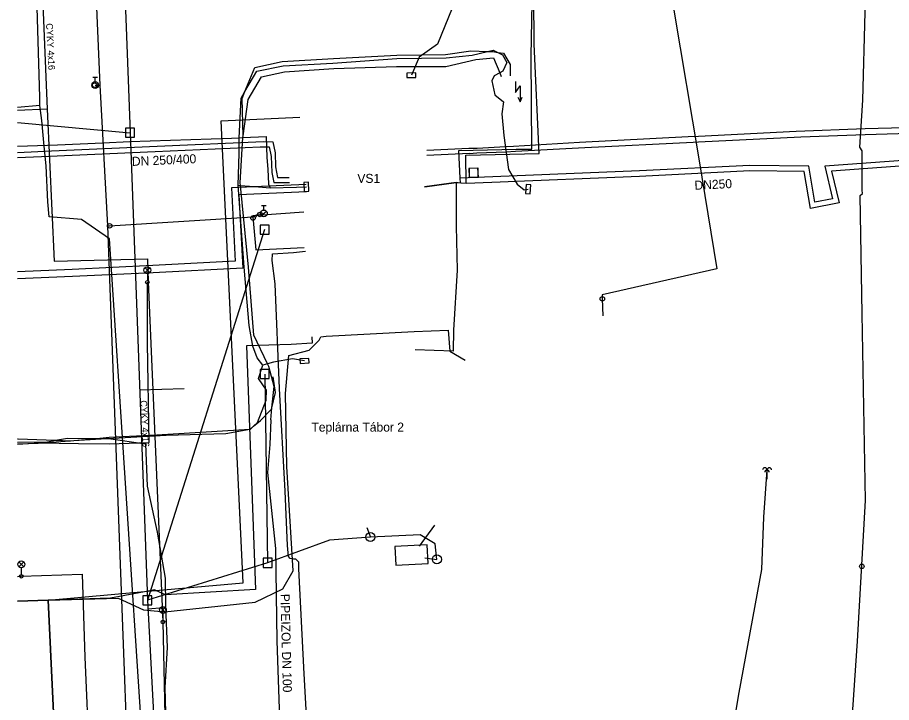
# Model space of a CAD drawing. Extents: x -736399 to -735926, y -1118992 to -1118244.
# Drawn here: x -736391.1 to -736294.2, y -1118749.6 to -1118673.7 of the extents above; entities that cross this region are included whole.
import ezdxf

# ---------------------------------------------------------------- set-up
doc = ezdxf.new("R2010")
doc.units = 0
for name, color, linetype in [('Hydranty', 7, 'Continuous'), ('Kabelovody skutečný průběh', 7, 'Continuous'), ('Kabelová skříň', 7, 'Continuous'), ('Kabelové skříně NN', 7, 'Continuous'), ('Kabelové vedení NN', 7, 'Continuous'), ('Kabelové vedení VN', 7, 'Continuous'), ('Kabelové vedení VO', 7, 'Continuous'), ('Kanalizační přípojky', 7, 'Continuous'), ('Kanalizační stoka', 7, 'Continuous'), ('Kanalizační šachty', 7, 'Continuous'), ('Nadz_ teplovodní potrubí', 7, 'Continuous'), ('Neurčené_doplňkové prvky', 7, 'Continuous'), ('Objekty nadzemní', 7, 'Continuous'), ('Osa trasy kynety', 7, 'Continuous'), ('Označník', 7, 'Continuous'), ('Plynová šoupata', 7, 'Continuous'), ('Podz_ teplovodní potrubí', 7, 'Continuous'), ('Popis teplovodu', 7, 'Continuous'), ('Popis VO', 7, 'Continuous'), ('Povrchové znaky VO', 7, 'Continuous'), ('STL plynovod', 7, 'Continuous'), ('Teplovodní kanál', 7, 'Continuous'), ('Teplovodní šachty', 7, 'Continuous'), ('Trafostanice_ rozvodny', 7, 'Continuous'), ('Vod přípojky-voda pitná', 7, 'Continuous'), ('Vod přípojky-voda užitková', 7, 'Continuous'), ('Vodovodní řad', 7, 'Continuous'), ('Vodovodní šoupata', 7, 'Continuous')]:
    doc.layers.add(name, color=color, linetype=linetype)

msp = doc.modelspace()

# ---------------------------------------------------------------- linework, layer by layer
at = {"layer": 'Hydranty'}
for p, q in [((-736382.69, -1118680.285), (-736382.19, -1118680.285)), ((-736382.44, -1118680.785), (-736382.44, -1118680.285)), ((-736364.034, -1118695.611), (-736363.444, -1118695.148)), ((-736363.99, -1118694.505), (-736363.49, -1118694.505)), ((-736363.74, -1118695.005), (-736363.74, -1118694.505))]:
    msp.add_line(p, q, dxfattribs=at)
for centre in [(-736382.44, -1118681.16), (-736363.74, -1118695.38)]:
    msp.add_circle(centre, 0.375, dxfattribs=at)
at = {"layer": 'Kabelovody skutečný průběh'}
for points in [[(-736387.66, -1118738.22), (-736391.053, -1118738.342)], [(-736383.35, -1118828.51), (-736387.66, -1118738.22)]]:
    msp.add_lwpolyline(points, dxfattribs=at)
at = {"layer": 'Kabelová skříň'}
msp.add_lwpolyline([(-736347.884, -1118680.332), (-736346.884, -1118680.308), (-736346.896, -1118679.808), (-736347.896, -1118679.832)], close=True, dxfattribs=at)
at = {"layer": 'Kabelové skříně NN'}
for points in [[(-736359.297, -1118691.95), (-736359.262, -1118692.949), (-736358.762, -1118692.931), (-736358.797, -1118691.932)], [(-736334.664, -1118692.193), (-736334.734, -1118693.191), (-736334.235, -1118693.226), (-736334.165, -1118692.228)], [(-736358.764, -1118711.444), (-736359.762, -1118711.496), (-736359.736, -1118711.996), (-736358.738, -1118711.943)]]:
    msp.add_lwpolyline(points, close=True, dxfattribs=at)
at = {"layer": 'Kabelové vedení NN'}
for points in [[(-736366.49, -1118687), (-736366.27, -1118682.61), (-736365.836, -1118681.872), (-736364.51, -1118679.62), (-736361.62, -1118679.03), (-736356.1, -1118678.73), (-736348.99, -1118678.23), (-736343.52, -1118678.15), (-736340.67, -1118677.83), (-736338.971, -1118677.432), (-736338.32, -1118677.28), (-736337.802, -1118677.539), (-736337.28, -1118677.8), (-736336.82, -1118678.64), (-736337.25, -1118679.62), (-736337.597, -1118679.804), (-736338.23, -1118680.14), (-736338.46, -1118680.68), (-736338.16, -1118682.23), (-736337.17, -1118683.03)], [(-736337.17, -1118683.03), (-736337.38, -1118684.36), (-736337.13, -1118686.76), (-736336.62, -1118690.51), (-736335.66, -1118692.13), (-736334.91, -1118692.75), (-736334.45, -1118692.71)], [(-736391.053, -1118687.946), (-736386.62, -1118687.78), (-736381.61, -1118687.56), (-736378.61, -1118687.43), (-736367.34, -1118687.04), (-736366.49, -1118687)], [(-736366.58, -1118692.25), (-736366.48, -1118688.73), (-736366.49, -1118687)], [(-736366.49, -1118687), (-736366.061, -1118686.981), (-736363.49, -1118686.87), (-736363.43, -1118689.2), (-736363.32, -1118690.48), (-736363.23, -1118692.13), (-736363.04, -1118692.53)], [(-736363.84, -1118712.19), (-736364.5, -1118711.37), (-736364.96, -1118710.1), (-736365.37, -1118707.79), (-736365.92, -1118701.35), (-736366.58, -1118692.25)], [(-736366.58, -1118692.25), (-736366.332, -1118692.27), (-736364.34, -1118692.43), (-736363.04, -1118692.53)], [(-736363.04, -1118692.53), (-736360.12, -1118692.46), (-736359.03, -1118692.44)], [(-736359.25, -1118711.72), (-736360.57, -1118711.48), (-736362.69, -1118711.88), (-736363.34, -1118712.055), (-736363.84, -1118712.19)], [(-736391.053, -1118720.896), (-736388.76, -1118720.85), (-736385.259, -1118720.587), (-736384.794, -1118720.552), (-736384.23, -1118720.51), (-736381.184, -1118720.327), (-736381.07, -1118720.32), (-736374.58, -1118719.94), (-736367.96, -1118719.76), (-736365.315, -1118719.275), (-736365.226, -1118719.258), (-736365.18, -1118719.25), (-736364.883, -1118718.973), (-736364.44, -1118718.56), (-736363.5, -1118716.08), (-736363.46, -1118714.98), (-736364.32, -1118713.68), (-736363.84, -1118712.19)], [(-736391.053, -1118720.718), (-736387.71, -1118720.69), (-736386.839, -1118720.524), (-736385.5, -1118720.27), (-736382.273, -1118720.313), (-736381.184, -1118720.327), (-736380.95, -1118720.33), (-736376.88, -1118720.92), (-736376.68, -1118725.6), (-736375.58, -1118730.69), (-736374.68, -1118735.79), (-736374.63, -1118738.91), (-736374.46, -1118743.49), (-736374.71, -1118747.93), (-736374.63, -1118750.7)]]:
    msp.add_lwpolyline(points, dxfattribs=at)
at = {"layer": 'Kabelové vedení VN'}
for points in [[(-736366.05, -1118686.8), (-736366.15, -1118682.63), (-736365.836, -1118681.872), (-736364.74, -1118679.23), (-736361.73, -1118678.54), (-736356.03, -1118678.2), (-736349.01, -1118677.86), (-736343.61, -1118677.78), (-736340.81, -1118677.38), (-736338.971, -1118677.432), (-736338.35, -1118677.45), (-736337.802, -1118677.539), (-736337.18, -1118677.64), (-736336.46, -1118678.88), (-736336.43, -1118680.15)], [(-736366.05, -1118686.8), (-736365.5, -1118682.74), (-736364.02, -1118680.24), (-736361.47, -1118679.71), (-736356, -1118679.33), (-736349.06, -1118679.09), (-736343.56, -1118679.09), (-736340.26, -1118678.34), (-736338.28, -1118678.15), (-736337.597, -1118679.804), (-736337.43, -1118680.21)], [(-736362.98, -1118718.26), (-736362.851, -1118716.939), (-736362.62, -1118714.56), (-736363.2, -1118712.35), (-736363.34, -1118712.055), (-736364.86, -1118708.86), (-736365.45, -1118701.34), (-736366.332, -1118692.27), (-736366.36, -1118691.98), (-736366.061, -1118686.981), (-736366.05, -1118686.8)], [(-736391.053, -1118720.36), (-736390.97, -1118720.36), (-736386.839, -1118720.524), (-736385.259, -1118720.587), (-736385.19, -1118720.59), (-736384.794, -1118720.552), (-736382.273, -1118720.313), (-736380.88, -1118720.18), (-736375.6, -1118719.93), (-736365.315, -1118719.275), (-736365.24, -1118719.27), (-736365.226, -1118719.258), (-736364.883, -1118718.973), (-736364.11, -1118718.33), (-736362.88, -1118717.06), (-736362.851, -1118716.939), (-736362.45, -1118715.24), (-736362.7, -1118713.48)], [(-736362.98, -1118718.26), (-736363.1, -1118720.97), (-736363.33, -1118724.1), (-736362.46, -1118732.51), (-736362.31, -1118742.76), (-736361.97, -1118752.45), (-736361.76, -1118760.37), (-736361.36, -1118768.45), (-736360.75, -1118781.08), (-736359.99, -1118796.77)]]:
    msp.add_lwpolyline(points, dxfattribs=at)
at = {"layer": 'Kabelové vedení VO'}
for points in [[(-736256.37, -1118617.77), (-736263.92, -1118623.01), (-736272.5, -1118630.07), (-736283.17, -1118636.62), (-736294.38, -1118641.55), (-736307.63, -1118648.53), (-736322.64, -1118657.67), (-736334.66, -1118664.32), (-736340.57, -1118666.94), (-736342.07, -1118670.59), (-736344.5, -1118676.64), (-736346.53, -1118678.08), (-736347.39, -1118680.07)], [(-736388.296, -1118671.266), (-736387.755, -1118683.837)], [(-736387.755, -1118683.837), (-736391.053, -1118683.979)], [(-736387.755, -1118683.837), (-736386.988, -1118700.659), (-736376.66, -1118700.413), (-736376.57, -1118702.96)], [(-736391.053, -1118720.945), (-736388.6, -1118720.81), (-736384.28, -1118720.87), (-736380.9, -1118720.91), (-736376.47, -1118720.76), (-736376.63, -1118709.75), (-736376.66, -1118703.01)], [(-736376.57, -1118702.96), (-736374.93, -1118740.65)], [(-736391.053, -1118735.606), (-736390.63, -1118735.59), (-736383.9, -1118735.35), (-736383.59, -1118744.54), (-736383.1, -1118755.62), (-736382.7, -1118765.21), (-736382.5, -1118768.83), (-736391.053, -1118769.14)], [(-736374.93, -1118740.65), (-736374.37, -1118766.6)]]:
    msp.add_lwpolyline(points, dxfattribs=at)
at = {"layer": 'Kanalizační přípojky'}
for points in [[(-736372.58, -1118714.82), (-736377.52, -1118714.95)], [(-736346.49, -1118732.24), (-736344.78, -1118729.94)], [(-736344.57, -1118733.72), (-736344.74, -1118732), (-736346.42, -1118731.01), (-736351.93, -1118731.24)], [(-736351.93, -1118731.24), (-736356.48, -1118731.59), (-736363.33, -1118734.1)], [(-736345.92, -1118733.53), (-736344.57, -1118733.72)], [(-736374.86, -1118739.1), (-736376.6, -1118739.24)]]:
    msp.add_lwpolyline(points, dxfattribs=at)
at = {"layer": 'Kanalizační stoka'}
for points in [[(-736379.98, -1118649.4), (-736378.58, -1118686.44)], [(-736391.053, -1118685.317), (-736378.58, -1118686.44)], [(-736378.58, -1118686.44), (-736376.65, -1118738.25)], [(-736363.66, -1118697.17), (-736376.65, -1118738.25)], [(-736363.65, -1118713.19), (-736363.33, -1118734.1)], [(-736363.33, -1118734.1), (-736376.65, -1118738.25)], [(-736376.65, -1118738.25), (-736374.7, -1118775.25), (-736374.15, -1118785.83), (-736373.94, -1118789.8)]]:
    msp.add_lwpolyline(points, dxfattribs=at)
at = {"layer": 'Kanalizační šachty'}
for p, q in [((-736378.08, -1118685.94), (-736379.08, -1118685.94)), ((-736379.08, -1118685.94), (-736379.08, -1118686.94)), ((-736378.08, -1118686.94), (-736378.08, -1118685.94)), ((-736379.08, -1118686.94), (-736378.08, -1118686.94)), ((-736363.16, -1118696.67), (-736364.16, -1118696.67)), ((-736364.16, -1118696.67), (-736364.16, -1118697.67)), ((-736363.16, -1118697.67), (-736363.16, -1118696.67)), ((-736364.16, -1118697.67), (-736363.16, -1118697.67)), ((-736363.15, -1118712.69), (-736364.15, -1118712.69)), ((-736364.15, -1118712.69), (-736364.15, -1118713.69)), ((-736363.15, -1118713.69), (-736363.15, -1118712.69)), ((-736364.15, -1118713.69), (-736363.15, -1118713.69)), ((-736362.83, -1118733.6), (-736363.83, -1118733.6)), ((-736363.83, -1118733.6), (-736363.83, -1118734.6)), ((-736362.83, -1118734.6), (-736362.83, -1118733.6)), ((-736363.83, -1118734.6), (-736362.83, -1118734.6)), ((-736376.15, -1118737.75), (-736377.15, -1118737.75)), ((-736377.15, -1118737.75), (-736377.15, -1118738.75)), ((-736376.15, -1118738.75), (-736376.15, -1118737.75)), ((-736377.15, -1118738.75), (-736376.15, -1118738.75))]:
    msp.add_line(p, q, dxfattribs=at)
for centre in [(-736351.93, -1118731.24), (-736344.57, -1118733.72)]:
    msp.add_circle(centre, 0.5, dxfattribs=at)
at = {"layer": 'Nadz_ teplovodní potrubí'}
for p, q in [((-736341.02, -1118688.2), (-736345.69, -1118688.4)), ((-736340.95, -1118688.75), (-736345.68, -1118688.96))]:
    msp.add_line(p, q, dxfattribs=at)
at = {"layer": 'Neurčené_doplňkové prvky'}
msp.add_line((-736307.97, -1118724.81), (-736307.97, -1118723.81), dxfattribs=at)
msp.add_lwpolyline([(-736318.09, -1118771.38), (-736313.65, -1118770.73), (-736313.25, -1118770.19), (-736313.01, -1118760.09), (-736311.06, -1118748.47), (-736308.55, -1118734.85), (-736308.32, -1118729.04), (-736307.97, -1118723.81)], dxfattribs=at)
for centre in [(-736308.22, -1118723.81), (-736307.97, -1118724.06), (-736307.72, -1118723.81)]:
    msp.add_arc(centre, 0.25, 0, 179.99999, dxfattribs=at)
at = {"layer": 'Objekty nadzemní'}
msp.add_lwpolyline([(-736349.11, -1118734.35), (-736345.53, -1118734.16), (-736345.66, -1118732.11), (-736349.23, -1118732.28), (-736349.11, -1118734.35)], dxfattribs=at)
at = {"layer": 'Osa trasy kynety'}
for points in [[(-736375.31, -1118826.617), (-736374.08, -1118826.617), (-736374.31, -1118812.667), (-736376.24, -1118777.737), (-736377.23, -1118753.457), (-736380.84, -1118698.187), (-736383.94, -1118696.047), (-736387.54, -1118695.767), (-736387.68, -1118694.087), (-736387.86, -1118690.097), (-736388.09, -1118687.917), (-736388.36, -1118685.097), (-736388.566, -1118683.41), (-736388.56, -1118682.517), (-736389.25, -1118660.127), (-736390.33, -1118624.317), (-736390.55, -1118620.227), (-736390.6, -1118618.137), (-736390.87, -1118614.807), (-736390.942, -1118613.428), (-736391.053, -1118611.927)], [(-736388.566, -1118683.41), (-736391.053, -1118683.631)], [(-736387.66, -1118738.22), (-736376.58, -1118737.24), (-736375.73, -1118737.16), (-736366.05, -1118736.3), (-736368.46, -1118685.11), (-736359.77, -1118684.71)], [(-736357.43, -1118709.04), (-736356.82, -1118709), (-736347.1, -1118708.45), (-736343.33, -1118708.32)], [(-736343.33, -1118708.32), (-736343.12, -1118710.63), (-736341.44, -1118711.63)], [(-736358.43, -1118709.06), (-736358.4, -1118709.75), (-736360.72, -1118709.9), (-736365.68, -1118710.04), (-736364.68, -1118737.07), (-736374.64, -1118737.65), (-736375.73, -1118737.16), (-736375.87, -1118737.1), (-736376.58, -1118737.24), (-736380.73, -1118738.03), (-736387.66, -1118738.22)], [(-736387.66, -1118738.22), (-736379.91, -1118738.03), (-736377.07, -1118739.3), (-736374.71, -1118739.52), (-736364.7, -1118738.45), (-736361.65, -1118736.97), (-736360.48, -1118734.97), (-736361.19, -1118723.43), (-736361.33, -1118715.33), (-736360.99, -1118711.14), (-736358.73, -1118710.53), (-736357.62, -1118709.42)], [(-736357.62, -1118709.42), (-736357.43, -1118709.04)], [(-736391.053, -1118738.342), (-736387.66, -1118738.22)], [(-736387.66, -1118738.22), (-736383.35, -1118828.51)]]:
    msp.add_lwpolyline(points, dxfattribs=at)
at = {"layer": 'Označník'}
for radius in [0.25, 0.0005]:
    msp.add_circle((-736297.461, -1118734.493), radius, dxfattribs=at)
at = {"layer": 'Plynová šoupata'}
msp.add_circle((-736326.233, -1118704.843), 0.25, dxfattribs=at)
at = {"layer": 'Podz_ teplovodní potrubí'}
for points in [[(-736341.98, -1118691.48), (-736342.12, -1118688.41), (-736335.79, -1118688.26), (-736334.06, -1118688.25), (-736334.11, -1118677.96), (-736333.87, -1118664.1), (-736334.03, -1118656.4), (-736334.24, -1118652.09), (-736334.76, -1118640.11), (-736335.56, -1118628.14), (-736336.12, -1118616.15), (-736336.83, -1118604.23), (-736337.48, -1118592.37)], [(-736341.32, -1118692.06), (-736341.36, -1118688.91), (-736333.22, -1118688.74), (-736333.8, -1118676.63), (-736333.86, -1118666.05), (-736333.28, -1118648.87), (-736330.74, -1118648.4), (-736331.22, -1118646.72), (-736333.23, -1118647.2), (-736333.73, -1118644.39), (-736334.69, -1118631.52), (-736335.19, -1118620.56), (-736336.01, -1118606.08), (-736336.81, -1118593.37)], [(-736220.79, -1118683.52), (-736232.82, -1118683.98), (-736236.94, -1118684.14), (-736239.32, -1118684.24), (-736244.73, -1118684.43), (-736256.78, -1118684.91), (-736268.74, -1118685.31), (-736280.76, -1118685.61), (-736292.72, -1118685.88), (-736297.11, -1118686.01), (-736304.76, -1118686.32), (-736315.56, -1118686.84), (-736316.72, -1118686.9), (-736328.75, -1118687.52), (-736336.07, -1118687.95), (-736336.97, -1118688), (-736340.11, -1118688.18), (-736341.02, -1118688.2)], [(-736340.95, -1118688.75), (-736340.13, -1118688.68), (-736336.91, -1118688.54), (-736335.87, -1118688.47), (-736328.18, -1118688.08), (-736316.17, -1118687.48), (-736315.56, -1118687.45), (-736304.21, -1118686.89), (-736297.1, -1118686.63), (-736292.21, -1118686.47), (-736280.17, -1118686.16), (-736268.21, -1118685.87), (-736256.2, -1118685.43), (-736244.23, -1118685.01), (-736239.55, -1118684.8), (-736236.95, -1118684.68), (-736232.28, -1118684.49), (-736220.19, -1118684.03)], [(-736391.053, -1118688.627), (-736387.29, -1118688.46), (-736375.58, -1118687.94), (-736363.8, -1118687.41), (-736362.74, -1118687.46), (-736362.49, -1118688.65), (-736362.44, -1118690.22), (-736362.22, -1118691.41), (-736360.94, -1118691.41)], [(-736238.53, -1118799.39), (-736240.09, -1118772.19), (-736240.84, -1118752.25), (-736241.75, -1118731.61), (-736242.1, -1118723.04), (-736246.25, -1118723.31), (-736246.65, -1118720.94), (-736242.02, -1118720.35), (-736242.18, -1118711.42), (-736242.65, -1118699.93), (-736243.59, -1118686.81), (-736246.88, -1118687.22), (-736252.09, -1118687.42), (-736269.68, -1118688.18), (-736283.24, -1118688.82), (-736301.55, -1118690.16), (-736300.72, -1118693.75), (-736302.67, -1118694.14), (-736303.35, -1118690.16), (-736309.88, -1118690.08), (-736322.12, -1118690.68), (-736341.98, -1118691.48)], [(-736239.16, -1118798.84), (-736240.69, -1118772.22), (-736241.44, -1118752.27), (-736242.35, -1118731.63), (-736242.67, -1118723.68), (-736246.75, -1118723.94), (-736247.34, -1118720.42), (-736242.63, -1118719.82), (-736242.78, -1118711.44), (-736243.25, -1118699.96), (-736244.14, -1118687.48), (-736246.83, -1118687.82), (-736252.07, -1118688.02), (-736269.65, -1118688.78), (-736283.2, -1118689.42), (-736300.81, -1118690.71), (-736299.99, -1118694.22), (-736303.16, -1118694.85), (-736303.86, -1118690.75), (-736309.87, -1118690.68), (-736322.09, -1118691.28), (-736338.46, -1118691.94), (-736341.32, -1118692.06)], [(-736391.053, -1118689.178), (-736387.49, -1118689.02), (-736375.79, -1118688.51), (-736364.14, -1118688), (-736363.14, -1118688), (-736362.92, -1118689.09), (-736362.86, -1118690.85), (-736362.63, -1118691.94), (-736360.91, -1118691.95)], [(-736359.06, -1118692.19), (-736367.34, -1118692.55), (-736366.93, -1118700.67), (-736376.04, -1118701.15), (-736385, -1118701.58), (-736391.053, -1118701.839)], [(-736342.43, -1118692.01), (-736342.43, -1118696.78), (-736342.31, -1118701.67), (-736342.74, -1118708.31), (-736342.75, -1118710.65), (-736346.99, -1118710.51)], [(-736345.93, -1118692.39), (-736342.43, -1118691.91), (-736341.96, -1118691.98)], [(-736342.43, -1118692.01), (-736345.92, -1118692.49)], [(-736341.32, -1118692.06), (-736342.43, -1118692.01)], [(-736341.96, -1118691.98), (-736341.98, -1118691.48)], [(-736359.01, -1118692.99), (-736366.5, -1118693.31), (-736366.09, -1118701.43), (-736376, -1118701.95), (-736384.96, -1118702.38), (-736391.053, -1118702.641)], [(-736357.23, -1118793.08), (-736357.7, -1118781.48), (-736358.16, -1118769.85), (-736358.63, -1118758.31), (-736359.27, -1118746.39), (-736359.88, -1118734.77), (-736359.88, -1118734.01), (-736360.2, -1118733.69), (-736360.45, -1118733.68), (-736360.81, -1118733.62), (-736361.01, -1118733.38), (-736361.12, -1118732.17), (-736361.37, -1118726.16), (-736362.01, -1118714.79), (-736362.5, -1118703.19), (-736362.81, -1118700.58), (-736362.78, -1118699.86), (-736360.45, -1118699.7), (-736359.12, -1118699.56)]]:
    msp.add_lwpolyline(points, dxfattribs=at)
at = {"layer": 'Povrchové znaky VO'}
for p, q in [((-736376.924, -1118701.948), (-736376.396, -1118701.42)), ((-736376.388, -1118701.945), (-736376.916, -1118701.416)), ((-736376.66, -1118702.06), (-736376.66, -1118702.81)), ((-736390.894, -1118734.528), (-736390.366, -1118734)), ((-736390.358, -1118734.525), (-736390.886, -1118733.996)), ((-736390.63, -1118734.64), (-736390.63, -1118735.39)), ((-736375.194, -1118739.588), (-736374.666, -1118739.06)), ((-736374.658, -1118739.585), (-736375.186, -1118739.056)), ((-736374.93, -1118739.7), (-736374.93, -1118740.45))]:
    msp.add_line(p, q, dxfattribs=at)
for centre, radius in [((-736376.66, -1118701.685), 0.375), ((-736376.66, -1118703.01), 0.2), ((-736390.63, -1118734.265), 0.375), ((-736390.63, -1118735.59), 0.2), ((-736374.93, -1118739.325), 0.375), ((-736374.93, -1118740.65), 0.2)]:
    msp.add_circle(centre, radius, dxfattribs=at)
at = {"layer": 'STL plynovod'}
for points in [[(-736264.3, -1118324.54), (-736324.9, -1118327.07), (-736362.75, -1118328.92), (-736362.72, -1118353.43), (-736363.18, -1118442.48), (-736363.1, -1118443.08), (-736358.85, -1118498.73), (-736356.97, -1118538.37), (-736358.37, -1118564.14), (-736356.14, -1118614.21), (-736354.04, -1118656.54), (-736337.05, -1118656.45), (-736321.09, -1118656.36), (-736315.54, -1118689.35), (-736313.54, -1118701.53), (-736326.25, -1118704.41), (-736326.233, -1118704.843)], [(-736299.36, -1118790.52), (-736299.94, -1118773.18), (-736299.67, -1118765.93), (-736299.08, -1118759.56), (-736297.93, -1118742.79), (-736297.05, -1118727.2), (-736297.43, -1118706.52), (-736297.65, -1118693.4), (-736297.4, -1118693.16), (-736297.42, -1118692.81), (-736297.42, -1118688.46), (-736297.68, -1118688.03), (-736297.37, -1118682.82), (-736296.85, -1118663.31), (-736296.75, -1118655.32), (-736296.95, -1118637.86), (-736297.06, -1118621.04), (-736296.52, -1118612.23), (-736295.81, -1118595.2)], [(-736326.233, -1118704.843), (-736326.16, -1118706.72)]]:
    msp.add_lwpolyline(points, dxfattribs=at)
at = {"layer": 'Teplovodní kanál'}
msp.add_lwpolyline([(-736339.97, -1118691.35), (-736340.01, -1118690.36), (-736341.04, -1118690.39), (-736341, -1118691.37), (-736339.97, -1118691.35)], dxfattribs=at)
at = {"layer": 'Teplovodní šachty'}
for p, q in [((-736340.005, -1118690.356), (-736341.004, -1118690.385)), ((-736341.004, -1118690.385), (-736340.975, -1118691.384)), ((-736339.976, -1118691.355), (-736340.005, -1118690.356)), ((-736340.975, -1118691.384), (-736339.976, -1118691.355))]:
    msp.add_line(p, q, dxfattribs=at)
at = {"layer": 'Trafostanice_ rozvodny'}
for points in [[(-736335.85, -1118680.75), (-736335.85, -1118682), (-736335.35, -1118681.25), (-736335.35, -1118683)], [(-736335.6, -1118682.5), (-736335.35, -1118683), (-736335.1, -1118682.5)]]:
    msp.add_lwpolyline(points, dxfattribs=at)
at = {"layer": 'Vod přípojky-voda pitná'}
for points in [[(-736364.92, -1118695.6), (-736359.33, -1118695.2)], [(-736364.96, -1118695.77), (-736364.64, -1118699.41), (-736359.29, -1118699.16)], [(-736364.92, -1118695.6), (-736364.94, -1118695.77)]]:
    msp.add_lwpolyline(points, dxfattribs=at)
at = {"layer": 'Vod přípojky-voda užitková'}
msp.add_lwpolyline([(-736352.33, -1118730.2), (-736351.93, -1118731.24)], dxfattribs=at)
at = {"layer": 'Vodovodní řad'}
for points in [[(-736382.45, -1118669.1), (-736381.92, -1118681.17)], [(-736382.44, -1118681.16), (-736382.25, -1118681.16)], [(-736382.25, -1118681.16), (-736381.92, -1118681.17)], [(-736381.92, -1118681.17), (-736381.06, -1118696.77)], [(-736380.84, -1118696.76), (-736364.96, -1118695.77), (-736364.94, -1118695.77), (-736364.9, -1118695.77), (-736364.56, -1118695.74)], [(-736364.58, -1118695.54), (-736364.17, -1118695.51)], [(-736364.56, -1118695.74), (-736364.58, -1118695.54)], [(-736364.17, -1118695.51), (-736363.74, -1118695.38)], [(-736381.06, -1118696.75), (-736380.84, -1118696.76)], [(-736381.06, -1118696.77), (-736377.18, -1118800.31)]]:
    msp.add_lwpolyline(points, dxfattribs=at)
at = {"layer": 'Vodovodní šoupata'}
for centre in [(-736382.5, -1118681.16), (-736364.17, -1118695.51), (-736364.95, -1118695.89), (-736380.84, -1118696.76)]:
    msp.add_circle(centre, 0.25, dxfattribs=at)

# ---------------------------------------------------------------- texts
at = {"layer": 'Popis teplovodu'}
for s, rotation, p in [('DN 250/400', 2.50237, (-736378.35, -1118690.12)), ('DN250', 2.81096, (-736315.99, -1118692.77)), ('PIPEIZOL DN 100', 271.40273, (-736361.898, -1118737.546))]:
    msp.add_text(s, height=1, rotation=rotation, dxfattribs=at).set_placement(p)
for s, p in [('VS1', (-736353.38, -1118692)), ('Teplárna Tábor 2', (-736358.47, -1118719.56))]:
    msp.add_text(s, height=1, dxfattribs=at).set_placement(p)
at = {"layer": 'Popis VO'}
for p in [(-736387.888, -1118674.331), (-736377.448, -1118716.111)]:
    msp.add_text('CYKY 4x16', height=0.75, rotation=272.89858, dxfattribs=at).set_placement(p)

doc.saveas('drawing.dxf')
